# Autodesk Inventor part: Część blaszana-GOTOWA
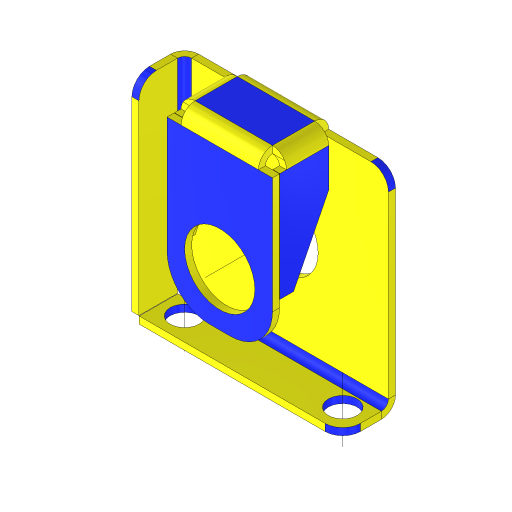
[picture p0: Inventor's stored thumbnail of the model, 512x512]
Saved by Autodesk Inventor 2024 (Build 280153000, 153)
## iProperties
Company: ATC
Created: 2023-03
Part Number: Część blaszana-GOTOWA
Material: Kurs-AJ
Document SubType Name: Konstrukcja blachowa
Designer: Andrzej Jaskulski
Density: 1 g/cm^3
Appearance: Żółta
Sheet Metal Rule: Domyślny
Flat Pattern Width: 9.30478 cm
Flat Pattern Length: 13.7572 cm
Flat Pattern Area: 128.007 cm^2
Sheet Metal Width: 93,048 mm
Sheet Metal Length: 137,572 mm
Sheet Metal Area: 12800,740 mm^2
Checked By: A.J.
Engr Approved By: Andrzej Jaskulski
Mfg Approved By: Andrzej Jaskulski
Authority: A.J.
Author: Andrzej Jaskulski
Title: A.J.: Kurs R2024-MEP
Revision Number: 1/24
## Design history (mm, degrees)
node "Powierzchnia1"
node "Kołnierz1"
node "Kołnierz2"
feature "Narożnik3" dims "d2" = 2 (= Grubość), "d23" = 8 (= RozmiarPodcięciaNarożnika), "d24" = 2 (= PromieńPrzejścia), "d25" = 0.1, "d26" = 0, "d27" = 10
node "Płaszczyzna konstrukcyjna1"
node "Powierzchnia2"
  sketch "Szkic4"
    geometry: L1 (15.054, 14.946)-(45.054, 14.946); L2 (45.054, 14.946)-(45.054, 42.011); L3 (45.054, 42.011)-(15.054, 42.011); L4 (15.054, 42.011)-(15.054, 14.946); L5 (0.054, 2.016)-(0.054, 59.946) reference; L6 (2.125, -0.054)-(60.054, -0.054) reference; L7 (60.054, 59.946)-(60.054, 3.946) reference
    constraints: 8 end point, 2 parallel, 1 horizontal, 1 perpendicular
    dimensions: "d29" = 15 distance between parallel lines of L5 L4; "d30" = 15 distance between parallel lines of L6 L1 (= d29); "d31" = 15 distance between parallel lines of L7 L2 (= d29)
feature "Zagięcie4" dims "d2" = 2 (= Grubość), "d37" = 2 (= SzerokośćGięciaPodcięcia), "d38" = 1 (= GłębokośćGięciaPodcięcia), "d39" = 4 (= MinimalnaPozostałość), "d40" = 2 (= PromieńPrzejścia), "d41" = 2 (= PromieńGięcia), "OdstępPołączenia" = 0.01
node "Kołnierz3"
node "Kołnierz4"
feature "Narożnik6" dims "d2" = 2 (= Grubość), "d62" = 8 (= RozmiarPodcięciaNarożnika), "d63" = 2 (= PromieńPrzejścia), "d64" = 0.1, "d65" = 0, "d66" = 10
feature "Narożnik7" dims "d2" = 2 (= Grubość), "d67" = 8 (= RozmiarPodcięciaNarożnika), "d68" = 2 (= PromieńPrzejścia), "d69" = 0.1, "d70" = 0, "d71" = 10
sketch "Szkic7"
  geometry: L1 (2.125, -0.054)-(60.054, -0.054) reference; L2 (0.054, 2.016)-(0.054, 59.946) reference; 1 further point
  dimensions: "d72" = 30 distance from line of L1 point (30.054, 29.946); "d73" = 30 distance from line of L2 point (30.054, 29.946)
hole "Otwór Piasty" sketch "Szkic7" diameter "d74" = 20; stored, may be unused: countersink angle "d78" = 90 deg, drill point angle "d80" = 118 deg; dims "d75" = 6, "d76" = 4, "d77" = 2, "d79" = 2 (= Grubość)
node "Oś otworu Piasty"
feature "Zaokrąglenie narożnika1" dims "d81" = 12
feature "Zaokrąglenie narożnika2" dims "d82" = 5
feature "Fazowanie narożnika1" dims "d83" = 10, "d84" = 20, angle "d85" = 45 deg
feature "Fazowanie narożnika2" dims "d86" = 10, "d87" = 20, angle "d88" = 45 deg
sketch "Szkic8"
  geometry: L1 (-4, 0)-(-4, 11) reference; L2 (56, 6)-(56, 0) reference; L3 (-1.929, 11)-(51, 11) reference; 2 further points
  constraints: 1 horizontal alignment
  dimensions: "d89" = 8.5 distance from line of L1 point (4.5, 4.5); "d90" = 6.5 distance from line of L2 point (49.5, 4.5); "d91" = 6.5 distance from line of L3 point (4.5, 4.5)
hole "Otwory Mocowania" sketch "Szkic8" diameter "d92" = 8.2; stored, may be unused: countersink angle "d96" = 90 deg, drill point angle "d98" = 118 deg; dims "d93" = 6, "d94" = 4, "d95" = 2, "d97" = 2 (= Grubość)
node "Oś otworu Mocowania-1"
node "Oś otworu Mocowania-2"
node "Bryła1"
sketch "Szkic1"
  geometry: L1 (0.054, -0.054)-(60.054, -0.054); L2 (60.054, -0.054)-(60.054, 59.946); L3 (60.054, 59.946)-(0.054, 59.946); L4 (0.054, 59.946)-(0.054, -0.054)
  constraints: 8 end point, 2 parallel, 1 horizontal, 1 perpendicular, 1 other
  dimensions: "d0" = 60 distance of L1.start L1.end; "d1" = 60 distance of L3.end L1.start
feature "Płyta1" dims "d2" = 2 (= Grubość)
sketch "Szkic2"
  geometry: L1 through (-30, 0) direction (1, -6.2e-35); L2 through (0, 7.5) direction (5.62e-35, 1); L3 (0, 15)-(-60, 15); L4 (-60, 15)-(-60, 0)
  constraints: 6 end point, 1 horizontal, 1 perpendicular, 1 vertical
feature "Płyta2" dims "d2" = 2 (= Grubość), "d3" = 2 (= SzerokośćGięciaPodcięcia), "d4" = 1 (= GłębokośćGięciaPodcięcia), "d5" = 4 (= MinimalnaPozostałość), "d6" = 2 (= PromieńPrzejścia), "d7" = 15, "d8" = 90 deg, "d9" = 2 (= PromieńGięcia), "d10" = 8 (= RozmiarPodcięciaNarożnika), "d11" = 2 (= Wielk_odstępu), "d12" = 2 (= Rozmiar_promienia_Jacobiego), "OdstępPołączenia" = 0.01
feature "Zagięcie1" dims "d2" = 2 (= Grubość), "d3" = 2 (= SzerokośćGięciaPodcięcia), "d4" = 1 (= GłębokośćGięciaPodcięcia), "d5" = 4 (= MinimalnaPozostałość), "d6" = 2 (= PromieńPrzejścia), "d7" = 15, "d8" = 90 deg, "d9" = 2 (= PromieńGięcia), "OdstępPołączenia" = 0.01
feature "Narożnik1" dims "d7" = 15, "d8" = 90 deg, "d10" = 8 (= RozmiarPodcięciaNarożnika), "d11" = 2 (= Wielk_odstępu), "d12" = 2 (= Rozmiar_promienia_Jacobiego)
sketch "Szkic3"
  geometry: L1 through (-28, 0) direction (1, 0); L2 through (0, 7.5) direction (0, 1); L3 (0, 15)-(-56, 15); L4 (-56, 15)-(-56, 0)
  constraints: 6 end point, 1 horizontal, 1 perpendicular, 1 vertical
feature "Płyta3" dims "d2" = 2 (= Grubość), "d13" = 2 (= SzerokośćGięciaPodcięcia), "d14" = 1 (= GłębokośćGięciaPodcięcia), "d15" = 4 (= MinimalnaPozostałość), "d16" = 2 (= PromieńPrzejścia), "d17" = 15, "d18" = 90 deg, "d19" = 2 (= PromieńGięcia), "d20" = 8 (= RozmiarPodcięciaNarożnika), "d21" = 2 (= Wielk_odstępu), "d22" = 2 (= Rozmiar_promienia_Jacobiego), "OdstępPołączenia" = 0.01
feature "Zagięcie2" dims "d2" = 2 (= Grubość), "d13" = 2 (= SzerokośćGięciaPodcięcia), "d14" = 1 (= GłębokośćGięciaPodcięcia), "d15" = 4 (= MinimalnaPozostałość), "d16" = 2 (= PromieńPrzejścia), "d17" = 15, "d18" = 90 deg, "d19" = 2 (= PromieńGięcia), "OdstępPołączenia" = 0.01
feature "Narożnik2" dims "d17" = 15, "d18" = 90 deg, "d20" = 8 (= RozmiarPodcięciaNarożnika), "d21" = 2 (= Wielk_odstępu), "d22" = 2 (= Rozmiar_promienia_Jacobiego)
feature "Płyta4" dims "d2" = 2 (= Grubość), "d32" = 2 (= PromieńGięcia), "d33" = 2 (= SzerokośćGięciaPodcięcia), "d35" = 4 (= MinimalnaPozostałość)
feature "Zagięcie3" dims "d2" = 2 (= Grubość), "d32" = 2 (= PromieńGięcia), "d33" = 2 (= SzerokośćGięciaPodcięcia), "d34" = 1 (= GłębokośćGięciaPodcięcia), "d35" = 4 (= MinimalnaPozostałość), "d36" = 2 (= PromieńPrzejścia), "OdstępPołączenia" = 0.01
sketch "Szkic5"
  geometry: L1 through (0, -6) direction (0, 1); L2 through (-17.5, 0) direction (-1, 0); L3 (-35, 0)-(-35, -12); L4 (-35, -12)-(0, -12)
  constraints: 6 end point, 1 horizontal, 1 perpendicular, 1 vertical
feature "Płyta5" dims "d2" = 2 (= Grubość), "d42" = 2 (= SzerokośćGięciaPodcięcia), "d43" = 1 (= GłębokośćGięciaPodcięcia), "d44" = 4 (= MinimalnaPozostałość), "d45" = 2 (= PromieńPrzejścia), "d46" = 35, "d47" = 90 deg, "d48" = 2 (= PromieńGięcia), "d49" = 8 (= RozmiarPodcięciaNarożnika), "d50" = 2 (= Wielk_odstępu), "d51" = 2 (= Rozmiar_promienia_Jacobiego), "OdstępPołączenia" = 0.01
feature "Zagięcie5" dims "d2" = 2 (= Grubość), "d42" = 2 (= SzerokośćGięciaPodcięcia), "d43" = 1 (= GłębokośćGięciaPodcięcia), "d44" = 4 (= MinimalnaPozostałość), "d45" = 2 (= PromieńPrzejścia), "d46" = 35, "d47" = 90 deg, "d48" = 2 (= PromieńGięcia), "OdstępPołączenia" = 0.01
feature "Narożnik4" dims "d46" = 35, "d47" = 90 deg, "d49" = 8 (= RozmiarPodcięciaNarożnika), "d50" = 2 (= Wielk_odstępu), "d51" = 2 (= Rozmiar_promienia_Jacobiego)
sketch "Szkic6"
  geometry: L1 through (0, 6) direction (0, -1); L2 through (17.5, 0) direction (1, 0); L3 (35, 0)-(35, 12); L4 (35, 12)-(0, 12)
  constraints: 6 end point, 1 horizontal, 1 perpendicular, 1 vertical
feature "Płyta6" dims "d2" = 2 (= Grubość), "d52" = 2 (= SzerokośćGięciaPodcięcia), "d53" = 1 (= GłębokośćGięciaPodcięcia), "d54" = 4 (= MinimalnaPozostałość), "d55" = 2 (= PromieńPrzejścia), "d56" = 35, "d57" = 90 deg, "d58" = 2 (= PromieńGięcia), "d59" = 8 (= RozmiarPodcięciaNarożnika), "d60" = 2 (= Wielk_odstępu), "d61" = 2 (= Rozmiar_promienia_Jacobiego), "OdstępPołączenia" = 0.01
feature "Zagięcie6" dims "d2" = 2 (= Grubość), "d52" = 2 (= SzerokośćGięciaPodcięcia), "d53" = 1 (= GłębokośćGięciaPodcięcia), "d54" = 4 (= MinimalnaPozostałość), "d55" = 2 (= PromieńPrzejścia), "d56" = 35, "d57" = 90 deg, "d58" = 2 (= PromieńGięcia), "OdstępPołączenia" = 0.01
feature "Narożnik5" dims "d56" = 35, "d57" = 90 deg, "d59" = 8 (= RozmiarPodcięciaNarożnika), "d60" = 2 (= Wielk_odstępu), "d61" = 2 (= Rozmiar_promienia_Jacobiego)
feature "Definicja1"
other parameters: "Grubość" = 2 (derived), "WspółczynnikK" = 4.4, "PromieńGięcia" = 2 (= Grubość), "SzerokośćGięciaPodcięcia" = 2 (= Grubość), "GłębokośćGięciaPodcięcia" = 1 (= 0.5 x Grubość), "RozmiarPodcięciaNarożnika" = 8 (= 4 x Grubość), "MinimalnaPozostałość" = 4 (= 2 x Grubość), "PromieńPrzejścia" = 2 (= PromieńGięcia), "Rozmiar_promienia_Jacobiego" = 2 (= Grubość), "Wielk_odstępu" = 2 (= Grubość), "Grubość" = 2, "GłębokośćGięciaPodcięcia" = 1, "MinimalnaPozostałość" = 4, "PromieńGięcia" = 2, "PromieńPrzejścia" = 2, "RozmiarPodcięciaNarożnika" = 8, "Rozmiar_promienia_Jacobiego" = 2, "SzerokośćGięciaPodcięcia" = 2, "Wielk_odstępu" = 2
